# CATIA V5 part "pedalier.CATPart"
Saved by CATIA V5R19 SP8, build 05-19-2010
Part number: pédalier
Bounding box of the stored display mesh (mm): x -100 to 10, y -130 to 130, z -14.995 to 14.995
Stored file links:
  G:\EU_thinkMotion\CFAO_2010\SIL_groupe1\SIL_groupe1\A reprendre\scador\monocycle\pedalier.CATPart
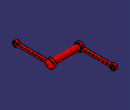
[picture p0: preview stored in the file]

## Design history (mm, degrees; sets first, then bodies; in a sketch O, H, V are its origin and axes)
Set1
  Point1: (-10, 20, 0)
  Point2: type OnCurve, Support Sketch6, RefPoint {extremum Reference Sketch6, Direction (1, 2, 3)}, Length 381.254
Body1 (main body)
  Sketch1 on yz-plane, origin (0, 0, 0), H (0, 1, 0), V (0, 0, 1)
    line L1 (-110.8348, 4) -> (-14.4568, 4)
    point P1 (-110.8348, 4)
    point P2 (-14.4568, 4)
    point P3 (-14.4568, -4)
    point P4 (-110.8348, -4)
    line L2 (-110.8348, -4) -> (-14.4568, -4)
    arc A1 centre (0, 0) radius 15 from (-14.4568, -4) to (-14.4568, 4) ccw
    point P5 (-14.4568, -4)
    point P6 (-120, 0)
    arc A2 centre (-120, 0) radius 10 from (-110.8348, 4) to (-110.8348, -4) ccw
    distance L1 L2 = 8
    distance O A1 = 15
    distance P6 A2 = 10
    distance P6 O = 120
    horizontal: L1 H
    symmetry: P2 P3 H, P1 P4 H, L1 L2 H
    coincidence: P3 P5
  Pad1: profile Sketch1, direction (1, 0, 0), length 10
  Sketch2 on start face of Pad1, origin (0, 0, 0), H (0, -1, 0), V (0, 0, 1)
    circle A1 centre (0, 0) radius 10
    radius A1 = 10
  Pad2: profile Sketch2, direction (-1, 0, 0), length 90
  Sketch3 on end face of Pad2, origin (-90, 0, 0), H (0, -1, 0), V (0, 0, 1)
    point P1 (-120, 0)
    line L1 (-110.8348, 4) -> (-14.4568, 4)
    point P2 (-110.8348, 4)
    point P3 (-14.4568, 4)
    point P4 (-14.4568, -4)
    point P5 (-110.8348, -4)
    line L2 (-110.8348, -4) -> (-14.4568, -4)
    arc A1 centre (-120, 0) radius 10 from (-110.8348, 4) to (-110.8348, -4) ccw
    arc A2 centre (0, 0) radius 15 from (-14.4568, -4) to (-14.4568, 4) ccw
    distance L1 L2 = 8
    distance P1 A1 = 10
    distance O A2 = 15
    distance P1 O = 120
    coincidence: P1 H
    horizontal: L1 H
    symmetry: P3 P4 H, P2 P5 H, L1 L2 H
  Pad3: profile Sketch3, direction (-1, 0, 0), length 10
  Sketch4 on end face of Pad3, origin (-100, 76.6518, 0), H (0, 1, 0), V (0, 0, -1)
    point P1 (43.3482, 0)
    reference projected arc E1 centre (43.3482, 0) radius 10 from (34.1831, -4) to (34.1831, 4) ccw from edge [face of Pad3 from Sketch3.A1 | end face of Pad3]
    reference projected arc E2 centre (43.3482, 0) radius 10 from (34.1831, -4) to (34.1831, 4) ccw from edge [face of Pad3 from Sketch3.A1 | end face of Pad3]
    distance P1 E1 = 10
    distance P1 E2 = 10
  Hole1: placed by Sketch4, at (-100, 120, 0) direction (1, 0, 0), diameter 10, depth 10
  Sketch5 on end face of Pad1, origin (10, -2.464, 4.2947), H (0, 1, 0), V (0, 0, 1)
    point P1 (-117.536, -4.2947)
    reference projected arc E1 centre (-117.536, -4.2947) radius 10 from (-108.3709, -0.2947) to (-108.3709, -8.2947) ccw from edge [face of Pad1 from Sketch1.A2 | end face of Pad1]
    distance P1 E1 = 10
  Hole2: placed by Sketch5, at (10, -120, 0) direction (-1, 0, 0), diameter 10, through (limit type 6)
  Fillet1: radius 1, on end face of Pad3
  Fillet2: radius 1, on end face of Pad1
  Fillet3: radius 1, on start face of Pad3
  Fillet4: radius 1, on start face of Pad1
  Sketch6 on start face of Pad1, origin (0, 0, 0), H (0, -1, 0), V (0, 0, 1)
    circle A1 centre (-20, 0) radius 80
    point P1 (-20, 0)
    radius A1 = 80
    coincidence: P1 H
